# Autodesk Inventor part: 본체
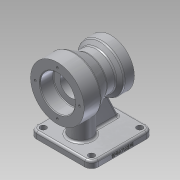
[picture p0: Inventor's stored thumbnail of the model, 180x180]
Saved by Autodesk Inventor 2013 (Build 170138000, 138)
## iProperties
Created: 2019-01
Part Number: 본체
Material: 알루미늄 6061
Document SubType Name: Modeling
Designer: Administrator
Density: 2.71 g/cm^3
Mass: 902.143 g
Surface Area: 600.963 cm^2
Volume: 332.894 cm^3
Author: Administrator
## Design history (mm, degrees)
sketch "스케치1"
  geometry: L1 (-30, 0)-(50, 0); L2 (-30, 0)-(-30, 40); L3 (-30, 40)-(-5, 40); L4 (-5, 40)-(15.785, 28); L5 (15.785, 28)-(29.126, 28); L6 (29.126, 28)-(35, 35); L7 (35, 35)-(50, 35); L8 (50, 35)-(50, 0); 1 further point
  constraints: 16 end point, 2 parallel, 2 perpendicular, 1 horizontal, 1 point on line, 1 vertical
  dimensions: "d0" = 25 distance of L2.end L3.end; "d2" = 80 distance between parallel lines of L8 L2; "d3" = 30 deg angle of L5 L4; "d4" = 50 deg angle of L5 L6; "d5" = 15 distance of L6.end L7.end; "d6" = 30 distance from line of L2 point (0, 0); "d7" = 80 diameter of L3 L1; "d8" = 70 diameter of L7 L1; "d9" = 56 diameter of L5 L1
revolve "회전1" sketch "스케치1" stored, may be unused: angle "d10" = 90 deg
hole "구멍1" diameter "d13" = 32; stored, may be unused: countersink angle "d17" = 90 deg, drill point angle "d19" = 118 deg; dims "d14" = 6, "d15" = 52, "d16" = 20, "d18" = 8, "d20" = 10, "d21" = 10
hole "구멍2" diameter "d24" = 40; stored, may be unused: countersink angle "d28" = 90 deg, drill point angle "d30" = 0 deg; dims "d22" = 10, "d23" = 10, "d25" = 6, "d26" = 66, "d27" = 20, "d29" = 17
node "작업 평면1"
sketch "스케치2"
  geometry: L1 (67, -46)-(-25, -46); L2 (-25, -46)-(-25, 46); L3 (-25, 46)-(67, 46); L4 (67, 46)-(67, -46); L5 (67, -46)-(-25, 46); L6 (-25, -46)-(67, 46); 2 further points
  constraints: 12 end point, 2 midpoint, 2 parallel, 2 perpendicular, 1 horizontal
  dimensions: "d32" = 92 distance of L2.end L3.end; "d34" = 25 distance from line of L2 point (0, 0); "d35" = 46 distance from line of L3 point (0, 0)
extrude "돌출1" join sketch "스케치2" distance "d36" = 10; taper "d37" = 0 deg
fillet "모깎기1" dims "d38" = 10
sketch "스케치3"
  geometry: A1 r 10 centre (57, 36) between (67, 36) and (57, 46) reference; A2 r 10 centre (-15, 36) between (-15, 46) and (-25, 36) reference; A3 r 10 centre (-15, -36) between (-25, -36) and (-15, -46) reference; A4 r 10 centre (57, -36) between (57, -46) and (67, -36) reference; 5 further points
  constraints: 4 coincident
hole "구멍3" sketch "스케치3" at (-15, 36), (-15, -36), (57, -36), (57, 36) diameter "d39" = 9; stored, may be unused: countersink angle "d43" = 90 deg, drill point angle "d45" = 0 deg; dims "d40" = 6, "d41" = 66, "d42" = 20, "d44" = 17
sketch "스케치4"
  geometry: L1 (-25, 36)-(-25, -36) reference; C1 r 16 at (5, 0); 1 further point
  constraints: 1 centre point, 1 horizontal alignment, 1 midpoint
  dimensions: "d46" = 32 diameter of C1; "d94" = 30 distance from line of C1.centre L1
extrude "돌출2" join sketch "스케치4" stored distance "d51" = 10; taper "d52" = 0 deg
sketch "스케치5"
  geometry: L1 (-57, -70)-(-42.992, -39.959); L2 (-57, -70)-(15, -70) reference; L3 (-67, -70)-(-57, -70) reference; L4 (-67, -70)-(-67, -80) reference; 1 further point
  constraints: 2 end point, 1 point on line
  dimensions: "d53" = 10 distance of L3.start L1.start; "d54" = 25 deg angle of L4 L1
feature "리브1" sketch "스케치5" dims "d55" = 1, "d56" = 10, "d57" = 0, "d58" = 0, "d59" = 1, "d60" = 1
sketch "스케치6"
  geometry: C1 r 26 at (0, 0) reference; 1 further point
  constraints: 1 horizontal alignment
  dimensions: "d61" = 33 distance of C1.centre point (33, 0)
hole "구멍4" sketch "스케치6" at (33, 0) diameter "d62" = 3.242; stored, may be unused: countersink angle "d66" = 90 deg, drill point angle "d68" = 118 deg; dims "d63" = 9, "d64" = 66, "d65" = 20, "d67" = 11
sketch "스케치7"
  geometry: C1 r 20 at (0, 0) reference; 1 further point
  constraints: 1 vertical alignment
  dimensions: "d72" = 27.5 distance of C1.centre point (0, 27.5)
hole "구멍5" sketch "스케치7" at (0, 27.5) diameter "d73" = 3.242; stored, may be unused: countersink angle "d77" = 90 deg, drill point angle "d79" = 118 deg; dims "d74" = 9, "d75" = 66, "d76" = 20, "d78" = 11
sketch "스케치8"
  geometry: L1 (72, 0)-(0, 0) reference; L2 (-10, 10)-(-10, 0) reference; 2 further points
  constraints: 1 other
  dimensions: "d83" = 4 distance from line of L1 point (36, 4); "d84" = 46 distance from line of L2 point (36, 4)
feature "엠보싱1" sketch "스케치8" dims "d32" = 92, "d34" = 25, "d35" = 46, "d85" = 0.5, "d86" = 0
fillet "모깎기2" dims "d87" = 3
fillet "모깎기3" dims "d88" = 3
chamfer "모따기1" distance "d89" = 1; stored, may be unused: second distance "d90" = 2, angle "d91" = 45 deg
fillet "모깎기4" dims "d92" = 1
fillet "모깎기5" dims "d93" = 0.6
node "솔리드1"
pattern_circular "원형 패턴1" dims angle "d70" = 360 deg
pattern_circular "원형 패턴2" dims angle "d81" = 360 deg
